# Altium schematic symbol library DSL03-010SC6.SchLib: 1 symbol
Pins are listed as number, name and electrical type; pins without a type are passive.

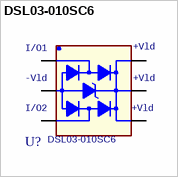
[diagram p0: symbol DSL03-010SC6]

## DSL03-010SC6
designator U?
footprint ST_SOT23-6L
pins: 1 I/O1, 2 -VLD, 3 I/O2, 4 +VLD, 5 +VLD1, 6 +VLD2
